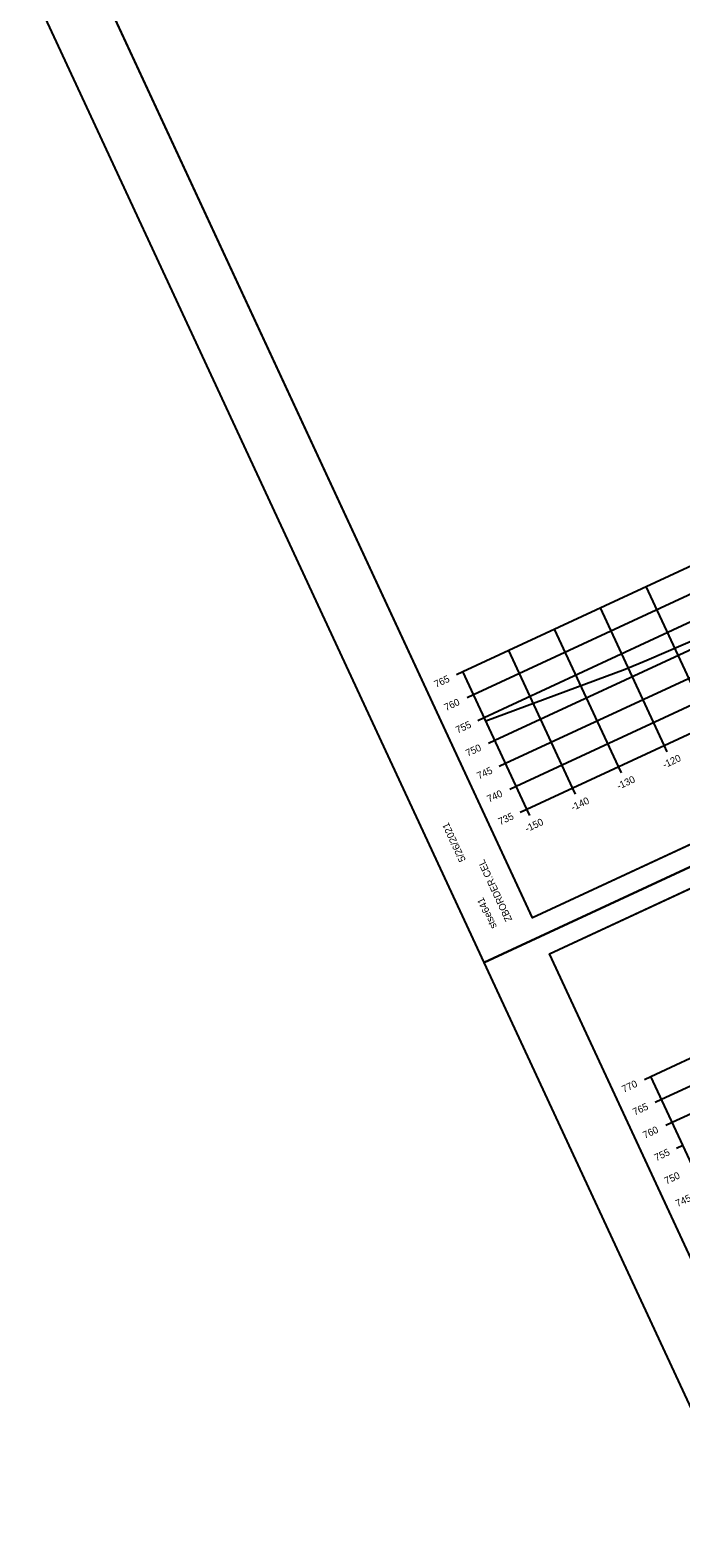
# Model space of a CAD drawing. Extents: x 1354696 to 1366163, y 660729 to 670380.
# Drawn here: x 1354695.9 to 1354824.6, y 664952.5 to 665250.9 of the extents above; entities that cross this region are included whole.
import ezdxf

# ---------------------------------------------------------------- set-up
doc = ezdxf.new("R2010")
doc.units = 0
for name, color, linetype in [('R_Axis', 7, 'Continuous'), ('R_Axis Annot', 7, 'Continuous'), ('R_Border', 7, 'Continuous'), ('R_Exist Surface', 7, 'Continuous'), ('R_Grid', 7, 'Continuous'), ('R_No Plot', 7, 'Continuous')]:
    doc.layers.add(name, color=color, linetype=linetype)

msp = doc.modelspace()

# ---------------------------------------------------------------- linework, layer by layer
at = {"layer": 'R_Axis'}
for p, q in [((1354794.15, 665096.77), (1355066.26, 665223.1)), ((1354780.25, 665123.39), (1354781.52, 665123.98)), ((1354794.15, 665096.77), (1354781.52, 665123.98)), ((1354782.36, 665118.86), (1354783.63, 665119.45)), ((1354784.46, 665114.32), (1354785.73, 665114.91)), ((1354786.57, 665109.79), (1354787.84, 665110.38)), ((1354821.95, 665108.13), (1354821.36, 665109.4)), ((1354788.67, 665105.25), (1354789.94, 665105.84)), ((1354812.88, 665103.92), (1354812.29, 665105.19)), ((1354790.78, 665100.72), (1354792.05, 665101.31)), ((1354803.81, 665099.71), (1354803.22, 665100.98)), ((1354792.88, 665096.18), (1354794.15, 665096.77)), ((1354794.74, 665095.5), (1354794.15, 665096.77)), ((1354817.45, 665043.27), (1354818.72, 665043.86)), ((1354835.56, 665007.58), (1354818.72, 665043.86)), ((1354819.55, 665038.73), (1354820.82, 665039.32)), ((1354821.66, 665034.2), (1354822.93, 665034.79)), ((1354823.77, 665029.66), (1354825.04, 665030.25))]:
    msp.add_line(p, q, dxfattribs=at)
at = {"layer": 'R_Border'}
for p, q in [((1354795.32, 665075.26), (1354708.8, 665261.62)), ((1355082.1, 665208.41), (1354795.32, 665075.26)), ((1354798.64, 665068.12), (1355085.42, 665201.26)), ((1354795.32, 665075.26), (1354795.32, 665075.26)), ((1354885.16, 664881.76), (1354798.64, 665068.12))]:
    msp.add_line(p, q, dxfattribs=at)
at = {"layer": 'R_Exist Surface'}
msp.add_lwpolyline([(1354786.04, 665114.25), (1354813.61, 665124.44), (1354817.93, 665126.22), (1354835.64, 665133.9)], dxfattribs=at)
at = {"layer": 'R_Grid'}
for p, q in [((1354781.52, 665123.98), (1355053.62, 665250.31)), ((1354783.63, 665119.45), (1355055.73, 665245.78)), ((1354785.73, 665114.91), (1355057.83, 665241.24)), ((1354787.84, 665110.38), (1355059.94, 665236.71)), ((1354789.94, 665105.84), (1355062.05, 665232.17)), ((1354792.05, 665101.31), (1355064.15, 665227.64)), ((1354794.15, 665096.77), (1355066.26, 665223.1)), ((1354818.72, 665043.86), (1355090.82, 665170.19)), ((1354820.82, 665039.32), (1355092.93, 665165.65)), ((1354822.93, 665034.79), (1355095.03, 665161.12)), ((1354830.43, 665113.62), (1354817.8, 665140.83)), ((1354821.36, 665109.4), (1354808.73, 665136.61)), ((1354812.29, 665105.19), (1354799.66, 665132.4)), ((1354803.22, 665100.98), (1354790.59, 665128.19)), ((1354794.15, 665096.77), (1354781.52, 665123.98)), ((1354835.56, 665007.58), (1354818.72, 665043.86))]:
    msp.add_line(p, q, dxfattribs=at)
at = {"layer": 'R_No Plot'}
for q in [(1355088.08, 665206.8), (1355088.09, 665206.79)]:
    msp.add_line((1354785.75, 665066.43), q, dxfattribs=at)
for points in [[(1354695.91, 665259.92), (1354998.25, 665400.29), (1355088.09, 665206.79), (1354785.74, 665066.42)], [(1354920.97, 665360.12), (1354938.76, 665368.38), (1354942.92, 665359.42), (1354957.54, 665366.21), (1354978.58, 665375.98), (1354990.55, 665350.49), (1355011.6, 665360.26), (1355082.1, 665208.41), (1354795.32, 665075.26), (1354708.8, 665261.62)], [(1354785.74, 665066.42), (1355088.09, 665206.79), (1355177.92, 665013.29), (1354875.58, 664872.92)], [(1355010.8, 665166.62), (1355028.6, 665174.88), (1355032.76, 665165.92), (1355047.37, 665172.71), (1355068.42, 665182.48), (1355080.38, 665156.99), (1355101.43, 665166.76), (1355171.94, 665014.91), (1354885.16, 664881.76), (1354798.64, 665068.12)]]:
    msp.add_lwpolyline(points, close=True, dxfattribs=at)

# ---------------------------------------------------------------- texts
at = {"layer": 'R_Axis Annot'}
for s, p in [('765', (1354776.22, 665120.75)), ('760', (1354778.21, 665116.16)), ('755', (1354780.49, 665111.7)), ('750', (1354782.48, 665107.12)), ('-120', (1354821.42, 665104.8)), ('745', (1354784.7, 665102.63)), ('-130', (1354812.35, 665100.59)), ('740', (1354786.69, 665098.05)), ('-140', (1354803.28, 665096.38)), ('735', (1354788.91, 665093.56)), ('-150', (1354794.21, 665092.17)), ('770', (1354813.36, 665040.6)), ('765', (1354815.52, 665036.09)), ('760', (1354817.52, 665031.5)), ('755', (1354819.79, 665027.05)), ('750', (1354821.79, 665022.46)), ('745', (1354824, 665017.98))]:
    msp.add_text(s, height=1.4, rotation=24.9042, dxfattribs=at).set_placement(p)
at = {"layer": 'R_Border'}
for s, p in [('5/26/2021', (1354782.14, 665086.7)), ('ZBORDER.CEL', (1354791.31, 665074.86)), ('stse641', (1354788.29, 665073.46))]:
    msp.add_text(s, height=1.4, rotation=114.9042, dxfattribs=at).set_placement(p)

doc.saveas('drawing.dxf')
